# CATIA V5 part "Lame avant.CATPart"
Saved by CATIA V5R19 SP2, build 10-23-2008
Part number: Lame avant
Bounding box of the stored display mesh (mm): x 0 to 670, y -7.5 to 7.5, z 0 to 15
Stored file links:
  C:\Users\Romain\Documents\IFMA\2A\cours\S3\Projet CFAO-IAO\CFAO\Catia\Organe de fixation\Lame avant.CATPart
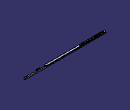
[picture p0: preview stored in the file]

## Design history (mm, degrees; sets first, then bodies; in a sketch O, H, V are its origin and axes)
Body1 (main body)
  Sketch1 on yz-plane, origin (0, 0, 0), H (0, 1, 0), V (0, 0, 1)
    line L1 (-4.5, 10) -> (-4.5, 0)
    point P1 (-4.5, 0)
    line L2 (-4.5, 0) -> (4.5, 0)
    line L3 (4.5, 0) -> (4.5, 10)
    line L4 (4.5, 10) -> (7.5, 10)
    line L5 (7.5, 15) -> (7.5, 10)
    line L6 (7.5, 15) -> (-7.5, 15)
    line L7 (-7.5, 15) -> (-7.5, 10)
    point P8 (-7.5, 10)
    line L8 (-7.5, 10) -> (-4.5, 10)
    length L2 = 9
    length L8 = 3
    length L4 = 3
    length L3 = 10
    length L5 = 5
    distance V L3 = 4.5
    coincidence: P1 H, P8 L4
    vertical: L1 V, L3 V, L5 V, L7 V
    horizontal: L2 H, L4 H, L6 H, L8 H
  Pad1: profile Sketch1, direction (1, 0, 0), length 670
  Sketch2 on face of Pad1 from Sketch1.L6, origin (0, 0, 15), H (1, 0, 0), V (0, 1, 0)
    line L1 (492.5838, -7.5) -> (500, -4.5)
    point P1 (492.5838, -7.5)
    line L2 (500, -4.5) -> (670, -4.5)
    point P3 (670, -4.5)
    reference projected line E1 (670, 7.5) -> (670, -7.5) from edge [face of Pad1 from Sketch1.L6 | end face of Pad1]
    reference projected line E2 (0, -7.5) -> (670, -7.5) from edge [face of Pad1 from Sketch1.L7 | face of Pad1 from Sketch1.L6]
    reference projected line E3 (0, -7.5) -> (670, -7.5) from edge [face of Pad1 from Sketch1.L7 | face of Pad1 from Sketch1.L6]
    length L2 = 170
    length L1 = 8
    distance L2 E3 = 3
    horizontal: L2 H
    coincidence: P3 E1, P1 E2
  Pocket1: profile Sketch2, direction (0, 0, -1), length 670
  Sketch3 on face of Pad1 from Sketch1.L6, origin (0, 0, 15), H (1, 0, 0), V (0, 1, 0)
    line L1 (492.5838, 7.5) -> (500, 4.5)
    point P1 (492.5838, 7.5)
    point P2 (500, 4.5)
    line L2 (500, 4.5) -> (670, 4.5)
    point P3 (500, 4.5)
    point P4 (670, 4.5)
    reference projected line E1 (670, 7.5) -> (670, -7.5) from edge [face of Pad1 from Sketch1.L6 | end face of Pad1]
    reference projected line E2 (0, 7.5) -> (670, 7.5) from edge [face of Pad1 from Sketch1.L6 | face of Pad1 from Sketch1.L5]
    reference projected line E3 (0, 7.5) -> (670, 7.5) from edge [face of Pad1 from Sketch1.L6 | face of Pad1 from Sketch1.L5]
    length L2 = 170
    distance L2 E2 = 3
    length L1 = 8
    horizontal: L2 H
    coincidence: P4 E1, P2 P3, E3 P1
  Pocket2: profile Sketch3, direction (0, 0, -1), length 670
  Sketch4 on face of Pad1 from Sketch1.L6, origin (0, 0, 15), H (1, 0, 0), V (0, 1, 0)
    line L1 (500, 4.5) -> (500, 2.5)
    point P1 (500, 4.5)
    line L2 (500, 2.5) -> (505, 2.5)
    line L3 (505, 2.5) -> (505, -2.5)
    line L4 (505, -2.5) -> (500, -2.5)
    point P5 (500, -2.5)
    line L5 (500, -2.5) -> (500, -4.5)
    point P6 (500, -4.5)
    reference projected line E1 (500, 4.5) -> (670, 4.5) from edge [face of Pad1 from Sketch1.L6 | face of Pocket2]
    reference projected line E2 (670, -4.5) -> (500, -4.5) from edge [face of Pad1 from Sketch1.L6 | face of Pocket1]
    reference projected point E3 (500, 4.5) from vertex [face of Pocket2 from Sketch3.L1 | face of Pocket2 | face of Pad1 from Sketch1.L6]
    length L2 = 5
    length L3 = 5
    length L1 = 2
    vertical: L1 V, L3 V, L5 V
    horizontal: L2 H, L4 H
    coincidence: P5 L1, P1 E1, P6 E2, P1 E3
  Pocket3: profile Sketch4, direction (0, 0, -1), length 5
  Sketch5 on end face of Pocket3, origin (603.9517, -3.6994, 10), H (1, 0, 0), V (0, 1, 0)
    point P1 (46.0483, 3.6994)
    reference projected line E1 (66.0483, 8.1994) -> (-103.9517, 8.1994) from edge [face of Pocket2 | end face of Pocket3]
    reference intersected line E2 (-103.9517, 6.1994) -> (-103.9517, 8.1994) from face of Pocket3 from Sketch4.L1
    distance P1 E1 = 4.5
    distance P1 E2 = 150
  Hole1: placed by Sketch5, at (650, 0, 10) direction (0, 0, -1), diameter 8, through (limit type 6)
  Sketch6 on face of Pad1 from Sketch1.L6, origin (0, 0, 15), H (1, 0, 0), V (0, 1, 0)
    line L1 (5, 7.5) -> (5, -7.5)
    point P1 (5, 7.5)
    point P2 (5, -7.5)
    reference projected line E1 (0, 7.5) -> (670, 7.5) from edge [face of Pad1 from Sketch1.L6 | face of Pad1 from Sketch1.L5]
    reference projected line E2 (0, -7.5) -> (670, -7.5) from edge [face of Pad1 from Sketch1.L7 | face of Pad1 from Sketch1.L6]
    reference projected line E3 (0, 7.5) -> (0, -7.5) from edge [start face of Pad1 | face of Pad1 from Sketch1.L6]
    reference projected line E4 (0, 7.5) -> (0, -7.5) from edge [start face of Pad1 | face of Pad1 from Sketch1.L6]
    distance E4 L1 = 5
    vertical: L1 V
    coincidence: P1 E1, P2 E2
    parallelism: L1 E3
  Pocket4: profile Sketch6, direction (0, 0, -1), length 10
  Fillet1: radius 1, on edge [start face of Pad1 | face of Pocket1]; edge [start face of Pad1 | face of Pocket2]; edge [face of Pocket3 from Sketch4.L2 | face of Pocket3 from Sketch4.L1]; edge [face of Pocket3 from Sketch4.L3 | face of Pocket3 from Sketch4.L2]; edge [face of Pocket3 from Sketch4.L4 | face of Pocket3 from Sketch4.L3]; edge [face of Pocket3 from Sketch4.L5 | face of Pocket3 from Sketch4.L4]; edge [face of Pocket1 from Sketch2.L1 | face of Pocket3 from Sketch4.L5]; edge [face of Pad1 from Sketch1.L7 | face of Pocket1 from Sketch2.L1]; edge [face of Pocket3 from Sketch4.L1 | face of Pocket2 from Sketch3.L1]; edge [face of Pocket2 from Sketch3.L1 | face of Pad1 from Sketch1.L5]
  Sketch7 on face of Pad1 from Sketch1.L6, origin (0, 0, 15), H (1, 0, 0), V (0, 1, 0)
    line L1 (15, 4) -> (21.875, 4)
    line L2 (21.875, 4) -> (21.875, -4)
    line L3 (21.875, -4) -> (15, -4)
    line L4 (15, -4) -> (15, 4)
    reference projected line E1 (0, 7.5) -> (670, 7.5) from edge [face of Pad1 from Sketch1.L6 | face of Pad1 from Sketch1.L5]
    reference projected line E2 (5, 7.5) -> (5, -7.5) from edge [face of Pocket4 from Sketch6.L1 | face of Pad1 from Sketch1.L6]
    length L2 = 8
    length L3 = 6.875
    distance L1 E1 = 3.5
    distance E2 L4 = 10
    horizontal: L1 H, L3 H
    vertical: L2 V, L4 V
  Pocket5: profile Sketch7, direction (0, 0, -1), length 8
  Fillet2: radius 1, on edge [face of Pocket5 from Sketch7.L3 | face of Pocket5 from Sketch7.L4]; edge [face of Pocket5 from Sketch7.L2 | face of Pocket5 from Sketch7.L3]; edge [face of Pocket5 from Sketch7.L4 | face of Pocket5 from Sketch7.L1]; edge [face of Pocket5 from Sketch7.L1 | face of Pocket5 from Sketch7.L2]
  RectPattern1: of Pocket5, Fillet2, direction 1 instances 16, spacing 12.875, along edge [face of Pad1 from Sketch1.L7 | face of Pad1 from Sketch1.L6]
  Sketch8 on end face of Pocket3, origin (0, 0, 10), H (1, 0, 0), V (0, 1, 0)
    line L1 (540, -2.5) -> (570, -2.5)
    line L2 (570, -2.5) -> (570, -7.5)
    line L3 (570, -7.5) -> (540, -7.5)
    line L4 (540, -7.5) -> (540, -2.5)
    reference intersected line E1 (500, -4.5) -> (500, -2.5) from face of Pocket3 from Sketch4.L5
    reference projected line E2 (500, -4.5) -> (670, -4.5) from edge [face of Pocket1 | end face of Pocket3]
    length L2 = 5
    length L1 = 30
    distance L4 E1 = 40
    distance L1 E2 = 2
    horizontal: L1 H, L3 H
    vertical: L2 V, L4 V
  Pad2: profile Sketch8, direction (0, 0, -1), length 10, opposite side length 5
  Fillet3: radius 1, on edge [face of Pad2 from Sketch8.L1 | face of Pad2 from Sketch8.L4]; edge [face of Pad2 from Sketch8.L2 | face of Pad2 from Sketch8.L1]; edge [face of Pad2 from Sketch8.L4 | face of Pad2 from Sketch8.L3]; edge [face of Pad2 from Sketch8.L3 | face of Pad2 from Sketch8.L2]; edge [face of Pocket1 | face of Pad2 from Sketch8.L2]; edge [face of Pad2 from Sketch8.L4 | face of Pocket1]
